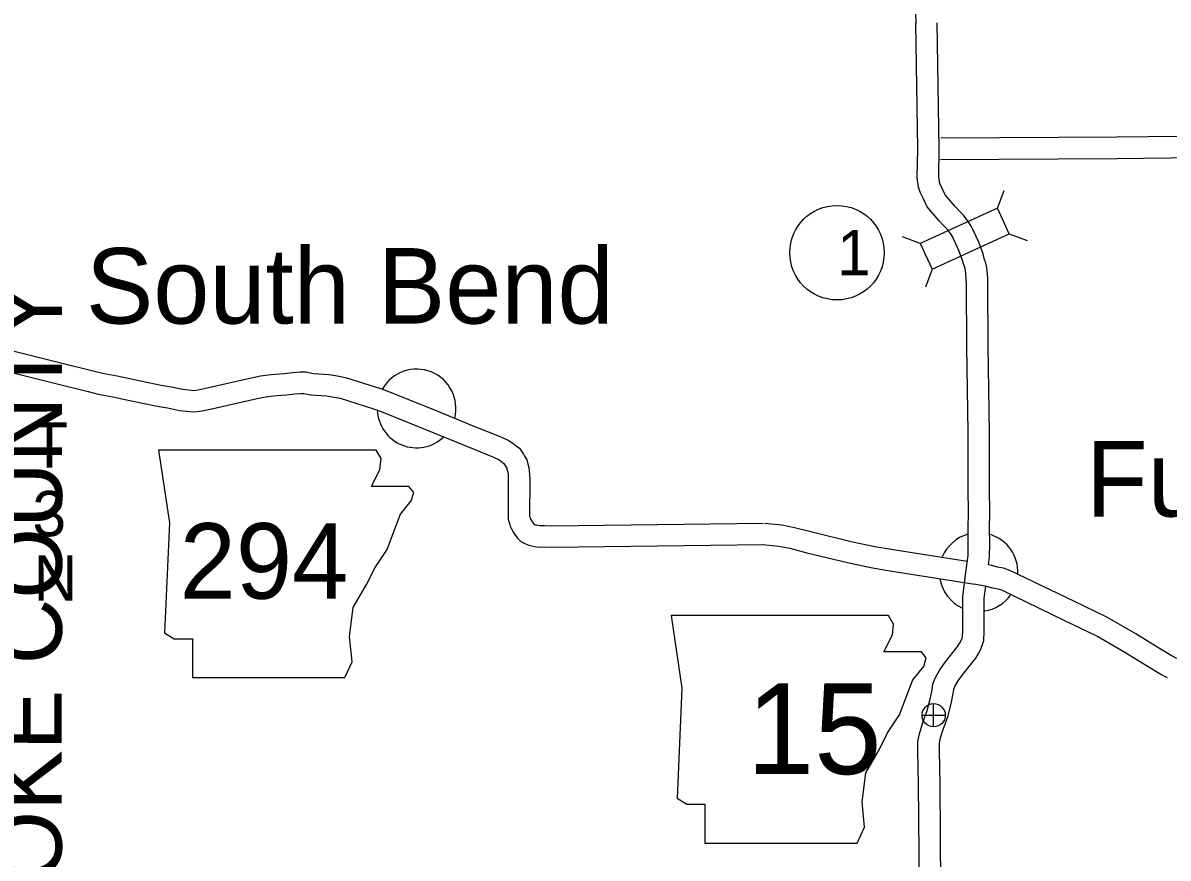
# Model space of a CAD drawing. Extents: x 1127717 to 1741049, y 2026793 to 2244711.
# Drawn here: x 1248173 to 1256180, y 2140586 to 2146423 of the extents above; entities that cross this region are included whole.
import ezdxf

# ---------------------------------------------------------------- set-up
doc = ezdxf.new("R2010")
doc.units = 0
for name, color, linetype in [('10', 7, 'Continuous'), ('20', 7, 'Continuous'), ('21', 7, 'Continuous'), ('24', 7, 'Continuous'), ('26', 7, 'Continuous'), ('27', 7, 'Continuous'), ('30', 7, 'Continuous'), ('Level 30', 7, 'Continuous')]:
    doc.layers.add(name, color=color, linetype=linetype)

msp = doc.modelspace()

# ---------------------------------------------------------------- linework, layer by layer
at = {"layer": '10'}
for points in [[(1254409.3, 2146648.1), (1254416.4, 2146419.3)], [(1254765.7, 2142584), (1254781.6, 2142701.8), (1254782.9, 2142782.3), (1254782.2, 2142894.5), (1254783.7, 2142995.6), (1254781.4, 2143171.9), (1254781.4, 2143560.8), (1254772.6, 2144163.8), (1254769.5, 2144597.3), (1254769.4, 2144636.4), (1254765.4, 2144672.4), (1254763.6, 2144690.2), (1254760.5, 2144707.1), (1254752, 2144733.3), (1254743.7, 2144761.8), (1254717.2, 2144833.2), (1254679.9, 2144914.6), (1254671.9, 2144930.4), (1254658.6, 2144952), (1254638.1, 2144979.7), (1254617.5, 2144999.4), (1254579, 2145040.8), (1254495.3, 2145138.5), (1254467.1, 2145198.1), (1254447.8, 2145240.2), (1254435.7, 2145275.9), (1254426.6, 2145341.1), (1254429.9, 2145544.3), (1254416.4, 2146420.5)], [(1254924, 2142635), (1254931.5, 2142690.5), (1254932.9, 2142781.6), (1254932.2, 2142893.9), (1254933.7, 2142995.4), (1254931.4, 2143172.9), (1254931.4, 2143561.9), (1254922.6, 2144165.4), (1254919.5, 2144597.9), (1254919.4, 2144645), (1254914.6, 2144688.1), (1254912.3, 2144711.2), (1254906.2, 2144744.2), (1254895.3, 2144777.7), (1254886.1, 2144809), (1254855.9, 2144890.6), (1254815.1, 2144979.7), (1254803, 2145003.5), (1254783, 2145036.2), (1254750.8, 2145079.4), (1254724.3, 2145104.7), (1254690.9, 2145140.7), (1254622.3, 2145220.8), (1254603.1, 2145261.3), (1254587.4, 2145295.6), (1254582.3, 2145310.6), (1254576.8, 2145350.3), (1254579.9, 2145544.2), (1254566.4, 2146422.8)], [(1254591.9, 2145619.7), (1255820.9, 2145626.1), (1257128.9, 2145642.2), (1258465, 2145662.5), (1259819.3, 2145672.8), (1261329.3, 2145704.8), (1262572.2, 2145746.8)], [(1254588.5, 2145469.7), (1255822.2, 2145476.1), (1257131, 2145492.2), (1258466.7, 2145512.6), (1259821.5, 2145522.8), (1261333.5, 2145554.9), (1262575.7, 2145596.8)], [(1248065.5, 2144141.6), (1248438.7, 2144048.5), (1248664.1, 2143992.1), (1248730.3, 2143976.1), (1248832, 2143956), (1248907.9, 2143939.4), (1248983.3, 2143923.6), (1249051.2, 2143910.1), (1249139.3, 2143892), (1249211.1, 2143879.5), (1249289.7, 2143863.7), (1249331.9, 2143859.8), (1249369.3, 2143855.2), (1249399, 2143859.2), (1249470.5, 2143875.1), (1249779.6, 2143945.8), (1249835.1, 2143956.4), (1249888.9, 2143962.6), (1249933.4, 2143968.1), (1250002.1, 2143973.1), (1250060.9, 2143980.6), (1250111.9, 2143983.8), (1250152.4, 2143983.5), (1250205.6, 2143973.8), (1250312.6, 2143965.2), (1250359.3, 2143958), (1250428.4, 2143945.4), (1250672.3, 2143868.3), (1250718.5, 2143852.2), (1251027.4, 2143727.6), (1251337.5, 2143601.2), (1251480.4, 2143543.1), (1251518.5, 2143527.4), (1251544.1, 2143516.1), (1251565.6, 2143506.5), (1251598.6, 2143487.1), (1251621, 2143467.7), (1251645.2, 2143450.8), (1251673.1, 2143408.4), (1251680.5, 2143395.4), (1251696.7, 2143369.7), (1251703.4, 2143338.9), (1251709.4, 2143315.1), (1251713.5, 2143292.6), (1251716.2, 2143267.9), (1251717.1, 2143232.4), (1251715.6, 2142974.9), (1251716.9, 2142970.4), (1251719.8, 2142962.5), (1251724.3, 2142952.3), (1251730.3, 2142941.1), (1251734.1, 2142935.8), (1251742.3, 2142923.7), (1251744.1, 2142921.2), (1251744.9, 2142920.7), (1251750.1, 2142918), (1251755.2, 2142916), (1251762.9, 2142914.1), (1251774.3, 2142911.7), (1251786.7, 2142910.3), (1251819, 2142911), (1251870.3, 2142908.9), (1253349.8, 2142927.5)], [(1248031.1, 2143995.6), (1248402.3, 2143903), (1248628.2, 2143846.5), (1248698.1, 2143829.5), (1248801.5, 2143809.1), (1248876.6, 2143792.7), (1248953.3, 2143776.7), (1249021.4, 2143763.1), (1249111.3, 2143744.6), (1249183.5, 2143732.1), (1249267.9, 2143715.1), (1249315.8, 2143710.6), (1249370.3, 2143703.9), (1249425.4, 2143711.5), (1249503.5, 2143728.8), (1249810.5, 2143798.9), (1249857.8, 2143808.1), (1249906.7, 2143813.7), (1249948.1, 2143818.8), (1250017.1, 2143823.8), (1250075.1, 2143831.2), (1250115.9, 2143833.8), (1250138.3, 2143833.6), (1250186.2, 2143824.9), (1250295, 2143816.1), (1250334.3, 2143810), (1250392.2, 2143799.5), (1250624.9, 2143725.9), (1250665.7, 2143711.7), (1250971, 2143588.5), (1251281, 2143462.2), (1251423.6, 2143404.2), (1251459.7, 2143389.4), (1251483.1, 2143379.1), (1251496.7, 2143373), (1251510.9, 2143364.7), (1251528.7, 2143349.3), (1251535.6, 2143344.4), (1251545.1, 2143330), (1251551.8, 2143318.1), (1251555.8, 2143311.9), (1251557.4, 2143304.7), (1251562.7, 2143283.5), (1251564.9, 2143271), (1251566.4, 2143257.7), (1251567.1, 2143231.1), (1251565.5, 2142953.8), (1251574.4, 2142923.4), (1251580.7, 2142906.3), (1251589.4, 2142886.5), (1251602.7, 2142861.8), (1251611, 2142850.2), (1251618.9, 2142838.3), (1251630.8, 2142821.6), (1251654, 2142799.8), (1251673.6, 2142788.7), (1251687.6, 2142781.5), (1251709.4, 2142772.7), (1251729.7, 2142767.8), (1251750.4, 2142763.4), (1251780, 2142760.1), (1251817.5, 2142761), (1251868.1, 2142758.9), (1253351.7, 2142777.5)], [(1253358.3, 2142927.1), (1253479.6, 2142914.8), (1253568.2, 2142897.7), (1253691.2, 2142865.6), (1253972.6, 2142797.1), (1254129.2, 2142764), (1254243.8, 2142745.1), (1254776, 2142660.2)], [(1253343.2, 2142777.9), (1253457.7, 2142766.2), (1253535, 2142751.3), (1253654.5, 2142720.1), (1253939.3, 2142650.9), (1254101.4, 2142616.5), (1254219.7, 2142597), (1254828.2, 2142499.9)], [(1254442.2, 2140382.4), (1254436.1, 2141101.7), (1254430.9, 2141335.4), (1254431.5, 2141400), (1254441.3, 2141454.5), (1254464.4, 2141533.2), (1254496, 2141617.7), (1254516.8, 2141696.6), (1254529.8, 2141762.4), (1254536, 2141804.7), (1254553.7, 2141848.4), (1254585.7, 2141907.4), (1254624.4, 2141958.5), (1254710.9, 2142067.9), (1254721.4, 2142085.8), (1254733.1, 2142106.5), (1254739.3, 2142121.9), (1254742.3, 2142131.8), (1254744.8, 2142175.7), (1254745.1, 2142412.6), (1254765.6, 2142582.9)], [(1256241.6, 2141982), (1256201.6, 2142001.3), (1256108.8, 2142058.7), (1255955, 2142152.4), (1255751.7, 2142269), (1255520, 2142382.5), (1255073.8, 2142597), (1255028.9, 2142611.9), (1254987.9, 2142619.3), (1254944.6, 2142631.3), (1254924, 2142635)], [(1254592.2, 2140381.1), (1254586.1, 2141104), (1254580.9, 2141336.3), (1254581.4, 2141386), (1254587.5, 2141420.1), (1254606.8, 2141485.8), (1254639.1, 2141572.2), (1254663.1, 2141662.9), (1254677.7, 2141737.1), (1254681.8, 2141765.2), (1254689.5, 2141784.3), (1254712.1, 2141825.8), (1254743, 2141866.7), (1254835, 2141983.1), (1254851.4, 2142010.9), (1254868.5, 2142041.1), (1254881.1, 2142072.2), (1254891, 2142105.7), (1254894.8, 2142171.3), (1254895.1, 2142403.6), (1254905, 2142486)], [(1256176.4, 2141846.9), (1256129.4, 2141869.6), (1256030.3, 2141930.8), (1255878.6, 2142023.2), (1255681.3, 2142136.5), (1255454.5, 2142247.5), (1255017.5, 2142457.7), (1254991.8, 2142466.1), (1254954.5, 2142472.9), (1254911.2, 2142484.9), (1254826.7, 2142500.2)]]:
    msp.add_lwpolyline(points, dxfattribs=at)
at = {"layer": '20'}
for p, q in [((1254987.4, 2145128.7), (1255033.4, 2145252.4)), ((1254447.5, 2144881.2), (1254323.7, 2144927.2)), ((1255069.9, 2144948.7), (1255193.7, 2144902.8)), ((1254530, 2144701.2), (1254484, 2144577.5))]:
    msp.add_line(p, q, dxfattribs=at)
msp.add_lwpolyline([(1254987.4, 2145128.7), (1254447.5, 2144881.2), (1254530, 2144701.2), (1255069.9, 2144948.7)], close=True, dxfattribs=at)
at = {"layer": '21'}
for points in [[(1249120.9, 2143437.5), (1249197, 2142930), (1249163.2, 2142160.2), (1249230.9, 2142117.9), (1249357.8, 2142117.9), (1249357.8, 2141847.3), (1250423.6, 2141847.3), (1250474.3, 2141957.2), (1250457.4, 2142134.9), (1250482.8, 2142337.9), (1250575.8, 2142498.6), (1250635.1, 2142617), (1250719.6, 2142743.9), (1250770.4, 2142879.2), (1250812.7, 2142989.2), (1250888.8, 2143082.3), (1250905.7, 2143141.5), (1250871.9, 2143183.8), (1250609.7, 2143183.8), (1250668.9, 2143302.2), (1250677.4, 2143378.3), (1250642.3, 2143436.8)], [(1252704.5, 2142281.3), (1252780.7, 2141773.7), (1252746.8, 2141004), (1252814.5, 2140961.7), (1252941.4, 2140961.7), (1252941.4, 2140691), (1254007.2, 2140691), (1254058, 2140800.9), (1254041, 2140978.6), (1254066.4, 2141181.6), (1254159.5, 2141342.3), (1254218.7, 2141460.7), (1254303.3, 2141587.6), (1254354, 2141723), (1254396.3, 2141832.9), (1254472.4, 2141926), (1254489.4, 2141985.2), (1254455.5, 2142027.5), (1254193.3, 2142027.5), (1254252.5, 2142145.9), (1254261, 2142222), (1254225.9, 2142280.5)]]:
    msp.add_lwpolyline(points, close=True, dxfattribs=at)
at = {"layer": '24'}
for centre, start, end in [((1250925.5, 2143728.5), 345.6773, 150.24667), ((1250925.5, 2143728.5), 182.23243, 313.69321), ((1254855.3, 2142584.7), 105.83499, 157.38702), ((1254855.3, 2142584.7), 357.59551, 72.64066), ((1254855.3, 2142584.7), 190.05928, 245.92107), ((1254855.3, 2142584.7), 278.88891, 324.42118)]:
    msp.add_arc(centre, 275, start, end, dxfattribs=at)
at = {"layer": '26'}
for p, q in [((1254540.9, 2141503), (1254540.9, 2141665.5)), ((1254459.6, 2141584.2), (1254622.1, 2141584.2))]:
    msp.add_line(p, q, dxfattribs=at)
msp.add_circle((1254540.9, 2141584.2), 81.2, dxfattribs=at)
at = {"layer": '27'}
msp.add_circle((1253865.2, 2144817.2), 330, dxfattribs=at)

# ---------------------------------------------------------------- texts
at = {"layer": '21'}
for s, height, p in [('294', 528, (1249269.6, 2142398.7)), ('15', 633.6, (1253234.6, 2141173.6))]:
    msp.add_text(s, height=height, dxfattribs=at).set_placement(p)
at = {"layer": '24'}
for s, p in [('South Bend', (1248613.5, 2144321.8)), ('Furlow', (1255606, 2142973.4))]:
    msp.add_text(s, height=528, dxfattribs=at).set_placement(p)
at = {"layer": '27'}
msp.add_text('1', height=316.8, dxfattribs=at).set_placement((1253865.2, 2144658.8))
at = {"layer": '30'}
for s, p in [('T', (1248229.7, 2143313.9)), ('3', (1248239.6, 2142835.3)), ('N', (1248247.7, 2142384.8))]:
    msp.add_text(s, height=316.8, dxfattribs=at).set_placement(p)
at = {"layer": 'Level 30'}
msp.add_text('LONOKE COUNTY', height=475.199, rotation=89.9667, dxfattribs=at).set_placement((1248443.3, 2139114.5))

doc.saveas('drawing.dxf')
